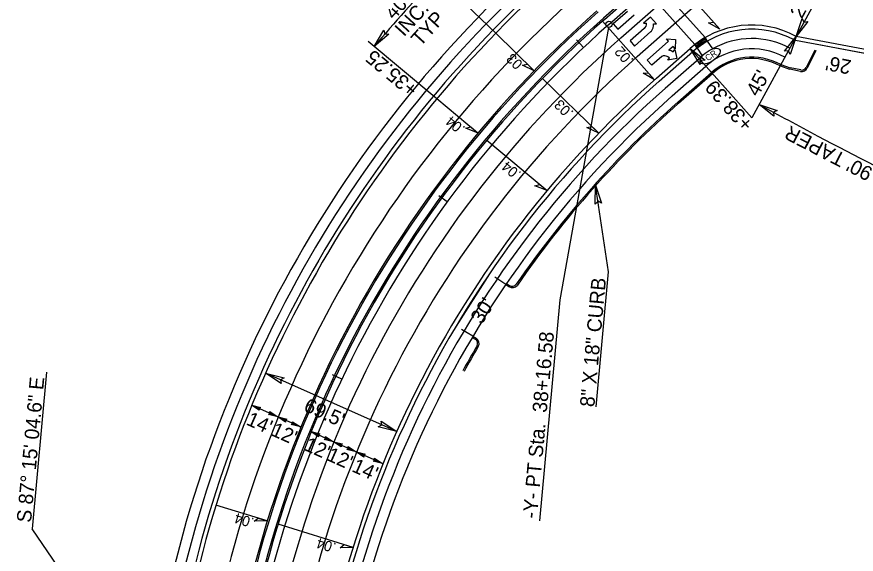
# Model space of a CAD drawing. Extents: x 2010838 to 2015151, y 441905 to 447792.
# Drawn here: x 2012540.8 to 2012947.2, y 446736.6 to 446996.9 of the extents above; entities that cross this region are included whole.
import ezdxf

# ---------------------------------------------------------------- set-up
doc = ezdxf.new("R2010")
doc.units = 0
for name, color, linetype in [('A-Wall-Abov', 7, 'Continuous'), ('A-Wall-Blow', 7, 'Continuous'), ('A-Wall-Comp', 7, 'Continuous'), ('B-Sheet Number', 7, 'Continuous'), ('C-Alignment Geometry', 7, 'Continuous'), ('C-Building', 7, 'Continuous'), ('C-CURB STOPS', 7, 'Continuous'), ('C-Grave Plots', 7, 'Continuous'), ('CLRD', 7, 'Continuous'), ('Cont-10-Lidar', 7, 'Continuous'), ('Cont-2-Lidar', 7, 'Continuous'), ('Default_10ft_LIDAR_Contou', 7, 'Continuous'), ('HATCH', 7, 'Continuous'), ('s-Existing Major', 7, 'Continuous'), ('S-Existing Minor', 7, 'Continuous'), ('S-overhead electric', 7, 'Continuous'), ('S-SITE LIGHT POLE REMOVE', 7, 'Continuous'), ('TEXT-LG', 7, 'Continuous'), ('TEXT-MED', 7, 'Continuous'), ('X2', 7, 'Continuous'), ('X4', 7, 'Continuous')]:
    doc.layers.add(name, color=color, linetype=linetype)

msp = doc.modelspace()

# ---------------------------------------------------------------- linework, layer by layer
at = {"layer": 'A-Wall-Abov'}
for p, q in [((2012836.42, 446999.47), (2012829.56, 446993.41)), ((2012831.75, 446990.94), (2012839.65, 446997.92)), ((2012847.6, 446996.8), (2012844.19, 446993.86)), ((2012850.47, 446993.47), (2012847.6, 446996.8)), ((2012829.56, 446993.41), (2012831.75, 446990.94)), ((2012844.19, 446993.86), (2012845.67, 446993.77)), ((2012848.99, 446993.56), (2012850.47, 446993.47)), ((2012844.56, 446991.25), (2012837.7, 446985.19)), ((2012839.89, 446982.72), (2012847.8, 446989.7)), ((2012837.7, 446985.19), (2012839.89, 446982.72)), ((2012845.97, 446975.93), (2012856.32, 446985.06)), ((2012856.32, 446985.06), (2012855.32, 446986.19)), ((2012855.32, 446986.19), (2012859.73, 446985.88)), ((2012859.73, 446985.88), (2012859.49, 446981.46)), ((2012858.5, 446982.59), (2012856.37, 446980.7)), ((2012859.49, 446981.46), (2012858.5, 446982.59)), ((2012858.58, 446979.85), (2012859.4, 446981.11)), ((2012859.4, 446981.11), (2012860.3, 446976.77)), ((2012848.16, 446973.45), (2012845.97, 446975.93)), ((2012852.99, 446977.72), (2012848.16, 446973.45)), ((2012855.96, 446975.87), (2012856.74, 446977.1)), ((2012860.3, 446976.77), (2012855.96, 446975.87))]:
    msp.add_line(p, q, dxfattribs=at)
for centre, radius, start, end in [((2012842.41, 446993.7), 3.28, 311.4451, 1.1033), ((2012843.78, 446993.06), 5.25, 320.1212, 5.4329), ((2012855.91, 446976.3), 4.43, 53.036, 83.9146), ((2012854.13, 446975.47), 2.52, 80.5183, 116.8303), ((2012854.08, 446973.55), 4.43, 53.1548, 84.0083)]:
    msp.add_arc(centre, radius, start, end, dxfattribs=at)
at = {"layer": 'A-Wall-Blow'}
for p, q in [((2012881.11, 446990.87), (2012854.28, 447021.26)), ((2012824.29, 446994.78), (2012849.51, 446966.36)), ((2012791.27, 446970.8), (2012772.61, 446988.9)), ((2012822.49, 446940.51), (2012795.22, 446966.97)), ((2012744.12, 446957.25), (2012764.08, 446940.59)), ((2012768.3, 446937.06), (2012797.48, 446912.72)), ((2012662.04, 446752.71), (2012637.2, 446760.38)), ((2012703.6, 446739.87), (2012667.29, 446751.08))]:
    msp.add_line(p, q, dxfattribs=at)
at = {"layer": 'A-Wall-Comp'}
for points in [[(2012881.11, 446990.87), (2012875.64, 446994.04), (2012878.05, 446994.34)], [(2012791.27, 446970.8), (2012785.57, 446973.54), (2012787.95, 446974.02)], [(2012849.51, 446966.36), (2012844.03, 446969.52), (2012846.44, 446969.82)], [(2012764.08, 446940.59), (2012758.19, 446942.9), (2012760.53, 446943.55)], [(2012822.49, 446940.51), (2012816.79, 446943.25), (2012819.17, 446943.73)], [(2012797.48, 446912.72), (2012791.59, 446915.03), (2012793.93, 446915.68)], [(2012662.04, 446752.71), (2012655.71, 446752.57), (2012657.62, 446754.07)], [(2012703.6, 446739.87), (2012697.28, 446739.73), (2012699.18, 446741.23)]]:
    msp.add_lwpolyline(points, close=True, dxfattribs=at)
at = {"layer": 'B-Sheet Number'}
for p, q in [((2012777.49, 446867.17), (2012772.2, 446870.77)), ((2012761.58, 446842.19), (2012756.1, 446845.45))]:
    msp.add_line(p, q, dxfattribs=at)
at = {"layer": 'C-Alignment Geometry'}
for p, q in [((2012873.97, 446986.8), (2012807.45, 447062.13)), ((2012868.96, 446983.42), (2012811.63, 447048.33))]:
    msp.add_line(p, q, dxfattribs=at)
at = {"layer": 'C-Building'}
for p, q in [((2012815.19, 446982.07), (2012811.76, 446985.71)), ((2012749.12, 446907.19), (2012745.08, 446910.14)), ((2012698.11, 446821.35), (2012693.6, 446823.49))]:
    msp.add_line(p, q, dxfattribs=at)
at = {"layer": 'C-CURB STOPS'}
msp.add_line((2012839.35, 447009.08), (2012824.79, 446996.23), dxfattribs=at)
for radius, end in [(543, 175.4266), (543, 175.4266), (539, 174.6039), (539, 174.6039)]:
    msp.add_arc((2013181.56, 446592.2), radius, 131.4451, end, dxfattribs=at)
at = {"layer": 'CLRD'}
msp.add_line((2012827.44, 446993.23), (2013068.81, 447206.37), dxfattribs=at)
msp.add_arc((2013181.56, 446592.2), 535, 131.4451, 175.4266, dxfattribs=at)
at = {"layer": 'Default_10ft_LIDAR_Contou'}
for p, q in [((2012827.16, 446991.75), (2012803.72, 446859.77)), ((2012803.72, 446859.77), (2012793.88, 446752.69)), ((2012555.14, 446824.81), (2012548.15, 446748.83)), ((2012614.67, 446651.52), (2012548.15, 446748.83))]:
    msp.add_line(p, q, dxfattribs=at)
msp.add_circle((2012827.44, 446993.23), 1.5, dxfattribs=at)
msp.add_circle((2012827.44, 446993.23), 1.5, dxfattribs=at)
at = {"layer": 'HATCH'}
for p, q in [((2012825.29, 446995.66), (2012856.34, 447023.08)), ((2012833.23, 446986.67), (2012868.23, 447017.57)), ((2012841.17, 446977.67), (2012876.41, 447008.79))]:
    msp.add_line(p, q, dxfattribs=at)
for radius, end in [(555.75, 175.4266), (543.75, 175.4266), (538.25, 174.6039), (526.25, 174.6039), (514.25, 175.4266)]:
    msp.add_arc((2013181.56, 446592.2), radius, 131.4451, end, dxfattribs=at)
at = {"layer": 's-Existing Major'}
for points in [[(2012923.74, 446994.59), (2012918.08, 446987.42), (2012920.99, 446996.14), (2012921.85, 446994.36)], [(2012720.8, 446988.43), (2012713.84, 446982.51), (2012718.41, 446990.48), (2012718.9, 446988.58)], [(2012912.42, 446980.26), (2012918.08, 446987.42), (2012915.16, 446978.71), (2012914.3, 446980.48)], [(2012871.59, 446973.85), (2012866.79, 446981.62), (2012873.98, 446975.9), (2012872.02, 446975.7)], [(2012907.31, 446948.78), (2012900.14, 446954.45), (2012908.86, 446951.53), (2012907.08, 446950.67)], [(2012820.79, 446906.19), (2012821.01, 446915.32), (2012823.92, 446906.6), (2012822.17, 446907.51)], [(2012668.82, 446819.24), (2012661.24, 446824.32), (2012670.15, 446822.09), (2012668.45, 446821.1)], [(2012658.11, 446806.27), (2012654.32, 446808.81), (2012658.78, 446807.7), (2012657.92, 446807.2)], [(2012663.31, 446805.65), (2012667.1, 446803.11), (2012662.64, 446804.22), (2012663.5, 446804.72)], [(2012670.9, 446800.57), (2012667.1, 446803.11), (2012671.56, 446802), (2012670.71, 446801.5)], [(2012674.27, 446800.76), (2012678.06, 446798.22), (2012673.6, 446799.33), (2012674.45, 446799.83)], [(2012717.12, 446801.09), (2012724.71, 446796.01), (2012715.79, 446798.23), (2012717.49, 446799.22)], [(2012686.88, 446793.44), (2012683.08, 446795.98), (2012687.54, 446794.87), (2012686.69, 446794.37)], [(2012690.25, 446793.63), (2012694.04, 446791.09), (2012689.58, 446792.2), (2012690.44, 446792.7)], [(2012697.84, 446788.55), (2012694.04, 446791.09), (2012698.5, 446789.98), (2012697.65, 446789.48)], [(2012701.21, 446788.74), (2012705, 446786.2), (2012700.54, 446787.31), (2012701.39, 446787.81)], [(2012708.8, 446783.66), (2012705, 446786.2), (2012709.46, 446785.09), (2012708.61, 446784.59)], [(2012713.99, 446783.04), (2012717.79, 446780.5), (2012713.33, 446781.61), (2012714.18, 446782.11)]]:
    msp.add_lwpolyline(points, close=True, dxfattribs=at)
at = {"layer": 'S-Existing Minor'}
for p, q in [((2012772.61, 446988.9), (2012742.23, 447018.37)), ((2012931.45, 447012.02), (2012918.08, 446987.42)), ((2012918.08, 446987.42), (2012896.58, 446947.89)), ((2012710.84, 446985.02), (2012744.12, 446957.25)), ((2012866.79, 446981.62), (2012896.58, 446947.89)), ((2012827.22, 446873.43), (2012821.01, 446915.32)), ((2012821.2, 446807.94), (2012827.22, 446873.43)), ((2012724.71, 446796.01), (2012661.24, 446824.32)), ((2012667.1, 446803.11), (2012654.32, 446808.81)), ((2012678.06, 446798.22), (2012667.1, 446803.11)), ((2012694.04, 446791.09), (2012683.08, 446795.98)), ((2012705, 446786.2), (2012694.04, 446791.09)), ((2012717.79, 446780.5), (2012705, 446786.2))]:
    msp.add_line(p, q, dxfattribs=at)
for centre, radius, start, end in [((2013182.44, 446591.46), 610.33, 135.8789, 140.15462), ((2014537.56, 449965.84), 3427.78, 241.46535, 242.0055), ((2013813.97, 448604.66), 1886.22, 242.0055, 243.88408)]:
    msp.add_arc(centre, radius, start, end, dxfattribs=at)
at = {"layer": 'S-overhead electric'}
for p, q in [((2013006.01, 446970.72), (2012918.08, 446987.42)), ((2012850.44, 446967.18), (2012866.79, 446981.62))]:
    msp.add_line(p, q, dxfattribs=at)
for centre, radius, start, end in [((2013181.56, 446592.2), 569.75, 132.2108, 169.9194), ((2012896.58, 446947.89), 45, 61.4653, 131.4451), ((2013181.56, 446592.2), 500.25, 131.4451, 175.4266)]:
    msp.add_arc(centre, radius, start, end, dxfattribs=at)
at = {"layer": 'S-SITE LIGHT POLE REMOVE'}
for p, q in [((2012927.07, 446980.81), (2012922.88, 446972.38)), ((2012927.67, 446980.51), (2012923.48, 446972.09)), ((2012910.46, 446973.08), (2012914.89, 446971.5)), ((2012910.68, 446973.72), (2012915.12, 446972.13)), ((2012920.23, 446970.47), (2012915.04, 446971.46)), ((2012920.36, 446971.13), (2012915.17, 446972.12)), ((2012860.75, 446955.5), (2012877.11, 446969.94)), ((2012861.2, 446955), (2012877.55, 446969.44)), ((2012777.49, 446867.17), (2012778.95, 446866.18)), ((2012777.87, 446867.72), (2012779.32, 446866.73)), ((2012761.24, 446841.61), (2012762.75, 446840.71)), ((2012761.58, 446842.19), (2012763.09, 446841.29))]:
    msp.add_line(p, q, dxfattribs=at)
for centre, radius, start, end in [((2012896.58, 446947.89), 29.42, 61.4653, 131.4451), ((2012896.58, 446947.89), 28.75, 61.4653, 131.4451), ((2012920.79, 446973.42), 3, 259.2418, 333.5661), ((2012920.79, 446973.42), 2.33, 259.2418, 333.5661), ((2013181.56, 446592.2), 484.67, 131.4451, 145.4116), ((2013181.56, 446592.2), 484, 131.4451, 145.4116), ((2012780.63, 446868.66), 3, 235.7645, 325.4116), ((2012780.63, 446868.66), 2.33, 235.7645, 325.4116), ((2012761.56, 446838.71), 3, 329.5896, 59.2367), ((2013181.56, 446592.2), 484.67, 149.5896, 151.2374), ((2013181.56, 446592.2), 484, 149.5896, 151.2374), ((2012761.56, 446838.71), 2.33, 329.5896, 59.2367)]:
    msp.add_arc(centre, radius, start, end, dxfattribs=at)
at = {"layer": 'TEXT-LG'}
for p, q in [((2012873.95, 446986.79), (2012868.98, 446983.43)), ((2012870.1, 446981.77), (2012868.98, 446983.43)), ((2012875.07, 446985.13), (2012870.1, 446981.77)), ((2012873.95, 446986.79), (2012875.07, 446985.13)), ((2012875.07, 446985.13), (2012877.6, 446981.38)), ((2012870.1, 446981.77), (2012872.62, 446978.03)), ((2012854.74, 446962.31), (2012871.1, 446976.75)), ((2012858.05, 446958.56), (2012874.41, 446973))]:
    msp.add_line(p, q, dxfattribs=at)
for centre in [(2012869.37, 446983.4), (2012869.85, 446983.72), (2012870.16, 446983.26), (2012870.35, 446984.05), (2012870.66, 446983.6), (2012870.82, 446984.37), (2012870.91, 446983.21), (2012871.14, 446983.92), (2012871.32, 446984.7), (2012871.39, 446983.53), (2012871.64, 446984.25), (2012871.64, 446983.18), (2012871.82, 446985.05), (2012871.89, 446983.87), (2012872.14, 446984.59), (2012872.14, 446983.52), (2012872.32, 446985.38), (2012872.39, 446984.21), (2012872.64, 446984.93), (2012872.64, 446983.86), (2012872.8, 446985.7), (2012872.89, 446984.54), (2012873.12, 446985.25), (2012873.14, 446984.19), (2012873.3, 446986.04), (2012873.37, 446984.86), (2012873.61, 446985.58), (2012873.62, 446984.51), (2012873.77, 446986.36), (2012873.87, 446985.2), (2012874.09, 446985.9), (2012874.11, 446984.85), (2012874.34, 446985.52), (2012874.59, 446985.17), (2012869.69, 446982.94), (2012869.94, 446982.56), (2012870.19, 446982.21), (2012870.42, 446982.88), (2012870.67, 446982.53), (2012871.16, 446982.86)]:
    msp.add_circle(centre, 0.0869, dxfattribs=at)
for centre, radius, start, end in [((2013181.56, 446592.2), 581.25, 132.20083, 172.15843), ((2013181.56, 446592.2), 576.25, 132.20083, 171.53405), ((2012896.58, 446947.89), 38.5, 61.4653, 119.5439), ((2012896.58, 446947.89), 33.5, 61.4653, 131.4451), ((2012896.58, 446947.89), 38.5, 128.4814, 131.4451), ((2013181.56, 446592.2), 493.75, 131.4451, 175.4266), ((2013181.56, 446592.2), 488.75, 131.4451, 175.4266)]:
    msp.add_arc(centre, radius, start, end, dxfattribs=at)
at = {"layer": 'TEXT-MED'}
for p, q in [((2013005.63, 446968.75), (2012917.7, 446985.46)), ((2012851.76, 446965.68), (2012868.12, 446980.12))]:
    msp.add_line(p, q, dxfattribs=at)
for centre, radius, start, end in [((2013181.56, 446592.2), 571.75, 132.2008, 169.9194), ((2012896.58, 446947.89), 43, 61.4653, 131.4451), ((2013181.56, 446592.2), 498.25, 131.4451, 175.4266)]:
    msp.add_arc(centre, radius, start, end, dxfattribs=at)
at = {"layer": 'X2'}
for p, q in [((2012953.77, 446978.61), (2012928.23, 446983.46)), ((2012769.67, 446872.38), (2012753.55, 446847.08))]:
    msp.add_line(p, q, dxfattribs=at)
at = {"layer": 'X4'}
msp.add_ellipse((2012876.41, 446977.84), major_axis=(4.64, 3.15), ratio=0.462467, dxfattribs=at)

# ---------------------------------------------------------------- texts
at = {"layer": 'A-Wall-Blow'}
for s, rotation, p in [('.02', 131.587, (2012839.62, 446976.07)), ('.03', 135.8708, (2012787.39, 446973.16)), ('.03', 135.8708, (2012810.6, 446950.78)), ('.04', 140.1546, (2012758.22, 446943.28)), ('.04', 140.1546, (2012785.33, 446921.37)), ('.04', 162.831, (2012656, 446753.94)), ('.04', 162.831, (2012695.74, 446741.82))]:
    msp.add_text(s, height=5, rotation=rotation, dxfattribs=at).set_placement(p)
at = {"layer": 'C-Grave Plots'}
for s, rotation, p in [("40'", 47.5064, (2012723.33, 446995.08)), ("28'", 61.4653, (2012920.83, 446995.59)), ('INC. ', 47.5064, (2012728.19, 446986.92)), ('TYP', 47.5064, (2012736.18, 446982.17)), ("26'", 169.2418, (2012945.15, 446975.78)), ("45'", 61.4653, (2012899.62, 446957.81)), ('+38.39', 131.454, (2012897.8, 446945.26)), ("90' TAPER", 152.5297, (2012955.77, 446923.26)), ("30'", 57.5007, (2012765.88, 446847.58)), ("69.5'", 335.9577, (2012679.17, 446806.14)), ("14'", 335.9577, (2012651.38, 446799.51)), ("12'", 335.9577, (2012663.34, 446794.36)), ("12'", 335.9577, (2012679.32, 446787.23)), ("12'", 335.9577, (2012690.28, 446782.34)), ("14'", 335.9577, (2012702.51, 446776.85))]:
    msp.add_text(s, height=7, rotation=rotation, dxfattribs=at).set_placement(p)
at = {"layer": 'Cont-10-Lidar'}
msp.add_text('8" X 18" CURB', height=7, rotation=84.7467, dxfattribs=at).set_placement((2012820.31, 446807.67))
at = {"layer": 'Cont-2-Lidar'}
msp.add_text('S 87%%d 15\' 04.6" E', height=7, rotation=84.7467, dxfattribs=at).set_placement((2012547.64, 446751.66))
at = {"layer": 'Default_10ft_LIDAR_Contou'}
msp.add_text('-Y- PT Sta.  38+16.58', height=7, rotation=84.7467, dxfattribs=at).set_placement((2012792.59, 446753.67))
at = {"layer": 'S-Existing Minor'}
msp.add_text('+35.25', height=7, rotation=140.1546, dxfattribs=at).set_placement((2012735.59, 446962.84))
at = {"layer": 'X4'}
msp.add_text('CR', height=3, rotation=34.1903, dxfattribs=at).set_placement((2012875.29, 446975.29))

doc.saveas('drawing.dxf')
